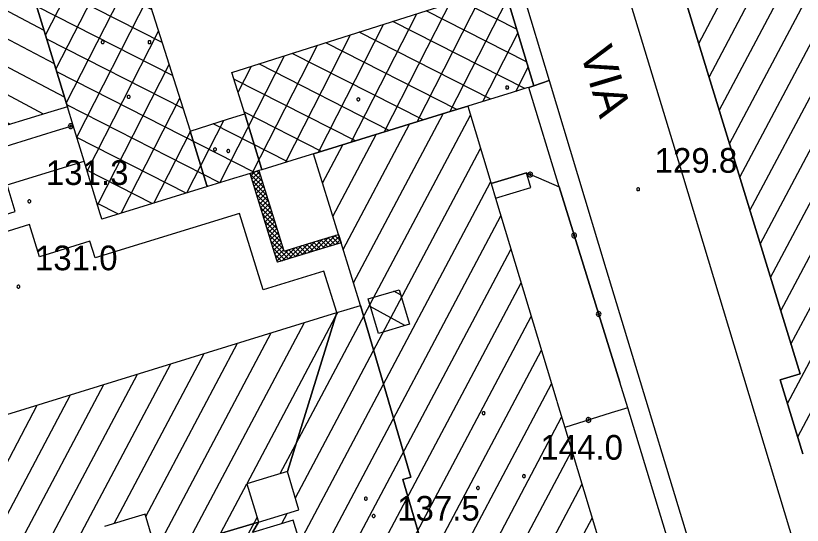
# Model space of a CAD drawing. Extents: x 513373 to 514978, y 5038576 to 5040180.
# Drawn here: x 513597.32 to 513645.09, y 5038663.13 to 5038694.11 of the extents above; entities that cross this region are included whole.
import ezdxf

# ---------------------------------------------------------------- set-up
doc = ezdxf.new("R2010")
doc.units = 0
for name, color, linetype in [('2010300', 7, 'Continuous'), ('3010204', 7, 'Continuous'), ('B1211', 7, 'Continuous'), ('C1131', 7, 'Continuous'), ('C12211', 7, 'Continuous'), ('C1228', 7, 'Continuous'), ('C211113', 7, 'Continuous'), ('C211132', 7, 'Continuous'), ('C2911', 7, 'Continuous'), ('C4114', 7, 'Continuous'), ('CAMP_C12211', 7, 'Continuous'), ('CAMP_C1228', 7, 'Continuous'), ('CAMP_C211132', 7, 'Continuous'), ('CAMP_C4114', 7, 'Continuous'), ('Default', 7, 'Continuous'), ('F12107', 7, 'Continuous'), ('F12131', 7, 'Continuous'), ('F12132', 7, 'Continuous'), ('TOP500', 7, 'Continuous'), ('TOP920', 7, 'Continuous')]:
    doc.layers.add(name, color=color, linetype=linetype)

# ---------------------------------------------------------------- blocks, each defined once
blk = doc.blocks.new('CAMP_2C1236C1')
at = {"layer": 'CAMP_C12211'}
for p, q in [((-31.743, -9.383), (-17.651, 17.232)), ((-32.365, -7.353), (-19.679, 16.607)), ((-32.987, -5.322), (-21.708, 15.982)), ((-31.121, -11.414), (-23.978, 2.077)), ((-30.499, -13.444), (-23.346, 0.066)), ((-29.877, -15.475), (-22.713, -1.945)), ((-29.255, -17.506), (-22.081, -3.957)), ((-28.633, -19.536), (-21.449, -5.968)), ((-28.011, -21.567), (-20.816, -7.979)), ((-27.388, -23.598), (-20.184, -9.991)), ((-27.6, -27.203), (-19.551, -12.002)), ((-26.978, -29.234), (-18.919, -14.013))]:
    blk.add_line(p, q, dxfattribs=at)
blk = doc.blocks.new('CAMP_D0075765')
at = {"layer": 'CAMP_C1228'}
for p, q in [((9.463, 3.83), (12.397, 9.588)), ((12.43, 9.48), (11.803, 9.8)), ((8.828, 5.888), (10.63, 9.424)), ((13.03, 7.491), (9.773, 9.15)), ((8.193, 7.945), (8.619, 8.781)), ((13.629, 5.502), (8.074, 8.333)), ((-13.783, 1.159), (-10.328, 7.941)), ((-8.617, 6.736), (-10.728, 7.812)), ((-14.413, 3.227), (-12.34, 7.294)), ((-13.153, -0.909), (-8.863, 7.511)), ((6.786, -4.73), (13.023, 7.512)), ((-7.98, 4.728), (-12.755, 7.161)), ((-15.043, 5.294), (-14.353, 6.648)), ((-7.343, 2.72), (-14.782, 6.51)), ((14.229, 3.513), (8.69, 6.335)), ((-12.523, -2.976), (-8.217, 5.475)), ((8.784, -4.112), (13.649, 5.437)), ((-6.706, 0.712), (-14.922, 4.898)), ((14.829, 1.524), (9.306, 4.338)), ((-11.893, -5.044), (-7.571, 3.439)), ((10.782, -3.495), (14.275, 3.361)), ((-6.068, -1.296), (-14.315, 2.906)), ((4.787, -5.347), (8.762, 2.453)), ((15.429, -0.465), (9.341, 2.637)), ((15.319, -2.093), (7.305, 1.99)), ((2.789, -5.964), (6.753, 1.815)), ((-11.263, -7.112), (-6.925, 1.403)), ((0.791, -6.582), (4.745, 1.178)), ((13.262, -2.728), (5.27, 1.344)), ((12.78, -2.877), (14.901, 1.286)), ((-5.431, -3.305), (-13.708, 0.913)), ((-1.207, -7.199), (2.737, 0.54)), ((11.205, -3.364), (3.234, 0.698)), ((9.149, -3.999), (1.198, 0.052)), ((-3.205, -7.816), (0.728, -0.097)), ((-10.633, -9.179), (-6.279, -0.633)), ((-2.086, -2.317), (-1.28, -0.735)), ((7.092, -4.635), (-0.838, -0.595)), ((14.778, -2.26), (15.527, -0.79)), ((-1.135, -7.177), (-13.101, -1.08)), ((5.035, -5.27), (-2.343, -1.511)), ((-9.199, -9.668), (-5.633, -2.669)), ((-3.192, -7.812), (-12.494, -3.073)), ((2.978, -5.906), (-1.704, -3.52)), ((-5.203, -8.434), (-2.956, -4.023)), ((0.922, -6.541), (-3.612, -4.232)), ((-7.201, -9.051), (-4.964, -4.661)), ((-5.249, -8.448), (-11.886, -5.066)), ((-7.305, -9.083), (-11.279, -7.059)), ((-9.362, -9.719), (-10.672, -9.052))]:
    blk.add_line(p, q, dxfattribs=at)
blk = doc.blocks.new('CAMP_AE7E8461')
at = {"layer": 'CAMP_C12211'}
for p, q in [((7.76, 8.621), (6.302, 9.393)), ((8.377, 6.597), (4.261, 8.776)), ((8.993, 4.573), (2.219, 8.16)), ((9.61, 2.55), (0.179, 7.543)), ((10.226, 0.526), (-1.863, 6.927)), ((10.843, -1.498), (-3.904, 6.31)), ((11.46, -3.522), (-5.945, 5.694)), ((10.188, -4.546), (-7.987, 5.077)), ((8.146, -5.162), (-10.028, 4.461)), ((6.105, -5.778), (-11.646, 3.62)), ((4.064, -6.395), (-11.036, 1.6)), ((2.023, -7.012), (-10.426, -0.42)), ((-0.018, -7.628), (-9.816, -2.441)), ((-2.06, -8.245), (-9.205, -4.461)), ((-4.101, -8.861), (-8.595, -6.481)), ((-6.142, -9.478), (-7.985, -8.502))]:
    blk.add_line(p, q, dxfattribs=at)
blk = doc.blocks.new('CAMP_13884420')
at = {"layer": 'CAMP_C12211'}
for p, q in [((3.521, 4.937), (14.114, 24.943)), ((7.011, 14.734), (12.456, 25.017)), ((6.386, 16.759), (10.427, 24.39)), ((5.76, 18.783), (8.397, 23.763)), ((5.135, 20.807), (6.368, 23.136)), ((3.486, 1.666), (14.73, 22.901)), ((3.759, -1.025), (15.346, 20.859)), ((-1.731, -14.6), (15.962, 18.817)), ((0.298, -13.973), (16.578, 16.775)), ((2.327, -13.346), (17.194, 14.733)), ((5.93, 12.693), (6.065, 12.948)), ((0.551, 2.533), (5.93, 12.693)), ((4.356, -12.719), (17.811, 12.691)), ((-3.398, -1.719), (4.036, 12.321)), ((-4.99, -1.52), (2.007, 11.694)), ((-5.604, 0.525), (-0.023, 11.066)), ((6.386, -12.092), (18.427, 10.65)), ((-7.523, 0.107), (-2.052, 10.439)), ((-12.88, -6.805), (-4.081, 9.812)), ((-13.494, -4.76), (-6.11, 9.185)), ((8.415, -11.465), (19.043, 8.608)), ((-13.916, -2.351), (-8.14, 8.558)), ((-15.597, -2.321), (-10.169, 7.931)), ((-19.19, -5.901), (-12.198, 7.304)), ((-19.815, -3.877), (-14.228, 6.677)), ((10.444, -10.838), (19.659, 6.566)), ((-20.441, -1.852), (-16.257, 6.05)), ((-21.066, 0.172), (-18.286, 5.423)), ((-21.692, 2.196), (-20.315, 4.796)), ((2.57, 3.14), (3.521, 4.937)), ((12.474, -10.211), (20.276, 4.524)), ((-1.379, -1.113), (0.542, 2.515)), ((13.962, -10.605), (20.892, 2.482)), ((2.658, 0.1), (2.988, 0.725)), ((0.639, -0.506), (1.156, 0.47)), ((14.588, -12.629), (21.508, 0.441)), ((-16.063, -16.022), (-7.934, -0.671)), ((-7.819, -16.481), (0.639, -0.506)), ((-9.849, -17.109), (-1.379, -1.113)), ((-5.416, -2.326), (-5.086, -1.702)), ((-4.529, -3.857), (-3.398, -1.719)), ((15.762, -13.618), (22.124, -1.601)), ((-7.435, -2.933), (-7.104, -2.309)), ((-5.79, -15.854), (1.428, -2.221)), ((-3.761, -15.227), (3.076, -2.314)), ((-15.437, -18.047), (-7.474, -3.007)), ((-17.452, -5.824), (-16.246, -3.547)), ((17.782, -13.008), (22.74, -3.643)), ((-15.509, -5.36), (-15.178, -4.735)), ((-11.878, -17.736), (-4.998, -4.741)), ((-13.907, -18.363), (-6.86, -5.053)), ((19.802, -12.399), (23.356, -5.685)), ((-18.564, -7.925), (-17.452, -5.824)), ((-17.939, -9.949), (-15.824, -5.955)), ((-16.688, -13.998), (-13.072, -7.168)), ((-17.314, -11.974), (-15.09, -7.775)), ((21.822, -11.789), (23.972, -7.727)), ((23.842, -11.179), (24.589, -9.769))]:
    blk.add_line(p, q, dxfattribs=at)
blk = doc.blocks.new('CAMP_5D255280')
at = {"layer": 'CAMP_C211132'}
for p, q in [((0.497, 0.583), (0.089, 0.807)), ((0.759, -1.273), (-1.345, -0.117))]:
    blk.add_line(p, q, dxfattribs=at)
blk = doc.blocks.new('CAMP_2C38B86D')
at = {"layer": 'CAMP_C4114'}
for p, q in [((-2.08, 3.138), (-1.86, 3.358)), ((-2.013, 2.922), (-1.56, 3.375)), ((-1.503, 3.19), (-1.716, 3.403)), ((-1.249, 2.37), (-2.108, 3.229)), ((-1.946, 2.706), (-1.493, 3.159)), ((-1.376, 2.78), (-1.932, 3.336)), ((-1.88, 2.49), (-1.426, 2.943)), ((-1.121, 1.96), (-1.982, 2.82)), ((-0.994, 1.55), (-1.855, 2.411)), ((-1.813, 2.274), (-1.359, 2.727)), ((-1.746, 2.058), (-1.293, 2.511)), ((-0.867, 1.14), (-1.729, 2.001)), ((-1.679, 1.842), (-1.226, 2.295)), ((-1.612, 1.626), (-1.159, 2.079)), ((-0.74, 0.73), (-1.602, 1.592)), ((-1.546, 1.409), (-1.092, 1.864)), ((-1.479, 1.193), (-1.025, 1.648)), ((-0.613, 0.32), (-1.476, 1.183)), ((-1.412, 0.977), (-0.958, 1.432)), ((-1.345, 0.761), (-0.891, 1.216)), ((-1.279, 0.545), (-0.824, 1)), ((-0.486, -0.09), (-1.349, 0.773)), ((-1.212, 0.329), (-0.757, 0.784)), ((-1.145, 0.113), (-0.69, 0.568)), ((-0.358, -0.5), (-1.223, 0.364)), ((-1.078, -0.103), (-0.623, 0.352)), ((-1.012, -0.319), (-0.556, 0.136)), ((-0.231, -0.91), (-1.096, -0.046)), ((-0.104, -1.32), (-0.97, -0.455)), ((-0.945, -0.535), (-0.489, -0.079)), ((-0.878, -0.751), (-0.422, -0.295)), ((0.216, -1.924), (-0.843, -0.864)), ((-0.811, -0.967), (-0.355, -0.511)), ((-0.744, -1.183), (-0.288, -0.727)), ((-0.678, -1.399), (-0.221, -0.943)), ((1.029, -1.673), (1.84, -0.861)), ((1.438, -1.546), (2.25, -0.735)), ((2.161, -1.323), (1.733, -0.895)), ((1.848, -1.42), (2.659, -0.608)), ((2.377, -1.256), (1.949, -0.828)), ((2.593, -1.189), (2.165, -0.761)), ((2.257, -1.293), (3.069, -0.482)), ((2.809, -1.123), (2.381, -0.694)), ((3.026, -1.056), (2.597, -0.627)), ((2.666, -1.167), (3.28, -0.553)), ((3.242, -0.989), (2.813, -0.561)), ((3.366, -0.831), (3.029, -0.494)), ((3.075, -1.041), (3.347, -0.769)), ((0, -1.99), (-0.717, -1.274)), ((-0.611, -1.615), (-0.154, -1.159)), ((-0.544, -1.832), (-0.087, -1.375)), ((-0.477, -2.048), (0.203, -1.368)), ((-0.199, -2.052), (0.612, -1.241)), ((0.432, -1.857), (0.005, -1.429)), ((0.211, -1.925), (1.022, -1.114)), ((0.649, -1.79), (0.221, -1.362)), ((0.865, -1.723), (0.437, -1.295)), ((0.62, -1.799), (1.431, -0.988)), ((1.081, -1.657), (0.653, -1.229)), ((1.297, -1.59), (0.869, -1.162)), ((1.513, -1.523), (1.085, -1.095)), ((1.729, -1.456), (1.301, -1.028)), ((1.945, -1.39), (1.517, -0.961)), ((-0.216, -2.057), (-0.59, -1.683)), ((-0.432, -2.124), (-0.464, -2.092))]:
    blk.add_line(p, q, dxfattribs=at)
blk = doc.blocks.new('03080200')
at = {"layer": 'Default'}
for p, q in [((-0.139, 0.046), (-0.146, 0)), ((-0.146, 0), (-0.139, -0.046)), ((-0.118, 0.086), (-0.139, 0.046)), ((-0.086, 0.118), (-0.118, 0.086)), ((-0.046, 0.139), (-0.086, 0.118)), ((0, 0.146), (-0.046, 0.139)), ((-0.042, 0.014), (-0.045, 0)), ((-0.045, 0), (-0.042, -0.014)), ((-0.036, 0.026), (-0.042, 0.014)), ((-0.026, 0.036), (-0.036, 0.026)), ((-0.014, 0.042), (-0.026, 0.036)), ((0, 0.045), (-0.014, 0.042)), ((0.046, 0.139), (0, 0.146)), ((0.014, 0.042), (0, 0.045)), ((0.026, 0.036), (0.014, 0.042)), ((0.036, 0.026), (0.026, 0.036)), ((0.042, 0.014), (0.036, 0.026)), ((0.045, 0), (0.042, 0.014)), ((0.042, -0.014), (0.045, 0)), ((0.086, 0.118), (0.046, 0.139)), ((0.118, 0.086), (0.086, 0.118)), ((0.139, 0.046), (0.118, 0.086)), ((0.146, 0), (0.139, 0.046)), ((0.139, -0.046), (0.146, 0)), ((-0.139, -0.046), (-0.118, -0.086)), ((-0.118, -0.086), (-0.086, -0.118)), ((-0.086, -0.118), (-0.046, -0.139)), ((-0.046, -0.139), (0, -0.146)), ((-0.042, -0.014), (-0.036, -0.026)), ((-0.036, -0.026), (-0.026, -0.036)), ((-0.026, -0.036), (-0.014, -0.042)), ((-0.014, -0.042), (0, -0.045)), ((0, -0.045), (0.014, -0.042)), ((0, -0.146), (0.046, -0.139)), ((0.014, -0.042), (0.026, -0.036)), ((0.026, -0.036), (0.036, -0.026)), ((0.036, -0.026), (0.042, -0.014)), ((0.046, -0.139), (0.086, -0.118)), ((0.086, -0.118), (0.118, -0.086)), ((0.118, -0.086), (0.139, -0.046))]:
    blk.add_line(p, q, dxfattribs=at)
blk = doc.blocks.new('08020400')
at = {"layer": 'Default'}
for p, q in [((-0.086, 0.028), (-0.09, 0)), ((-0.09, 0), (-0.086, -0.028)), ((-0.073, 0.053), (-0.086, 0.028)), ((-0.053, 0.073), (-0.073, 0.053)), ((-0.028, 0.086), (-0.053, 0.073)), ((0, 0.09), (-0.028, 0.086)), ((0.028, 0.086), (0, 0.09)), ((0.053, 0.073), (0.028, 0.086)), ((0.073, 0.053), (0.053, 0.073)), ((0.086, 0.028), (0.073, 0.053)), ((0.09, 0), (0.086, 0.028)), ((0.086, -0.028), (0.09, 0)), ((-0.086, -0.028), (-0.073, -0.053)), ((-0.073, -0.053), (-0.053, -0.073)), ((-0.053, -0.073), (-0.028, -0.086)), ((-0.028, -0.086), (0, -0.09)), ((0, -0.09), (0.028, -0.086)), ((0.028, -0.086), (0.053, -0.073)), ((0.053, -0.073), (0.073, -0.053)), ((0.073, -0.053), (0.086, -0.028))]:
    blk.add_line(p, q, dxfattribs=at)
blk = doc.blocks.new('NSIMB25')
at = {"layer": 'Default'}
for p, q in [((-0.086, 0.028), (-0.09, 0)), ((-0.09, 0), (-0.086, -0.028)), ((-0.073, 0.053), (-0.086, 0.028)), ((-0.053, 0.073), (-0.073, 0.053)), ((-0.028, 0.086), (-0.053, 0.073)), ((0, 0.09), (-0.028, 0.086)), ((0.028, 0.086), (0, 0.09)), ((0.053, 0.073), (0.028, 0.086)), ((0.073, 0.053), (0.053, 0.073)), ((0.086, 0.028), (0.073, 0.053)), ((0.09, 0), (0.086, 0.028)), ((0.086, -0.028), (0.09, 0)), ((-0.086, -0.028), (-0.073, -0.053)), ((-0.073, -0.053), (-0.053, -0.073)), ((-0.053, -0.073), (-0.028, -0.086)), ((-0.028, -0.086), (0, -0.09)), ((0, -0.09), (0.028, -0.086)), ((0.028, -0.086), (0.053, -0.073)), ((0.053, -0.073), (0.073, -0.053)), ((0.073, -0.053), (0.086, -0.028))]:
    blk.add_line(p, q, dxfattribs=at)
blk = doc.blocks.new('A$C3704598A')
at = {"layer": '2010300'}
blk.add_lwpolyline([(257.279, -696.425), (255.429, -690.383)], dxfattribs=at)
at = {"layer": '3010204'}
for points in [[(223.745, -696.313), (228.419, -694.868)], [(243.776, -704.079), (242.995, -701.55), (239.309, -702.688), (237.873, -698.042), (229.091, -700.755), (228.776, -699.737), (225.716, -700.682), (225.112, -698.727), (222.436, -699.554)]]:
    blk.add_lwpolyline(points, dxfattribs=at)
at = {"layer": 'B1211'}
for points in [[(314.878, -654.761), (269.808, -668.647), (269.785, -668.574), (269.568, -667.868), (268.566, -668.177), (258.4, -671.309), (261.926, -682.527), (261.949, -682.598), (262.994, -682.277), (263.997, -681.97), (271.91, -707.801), (270.707, -708.17), (272.084, -712.665)], [(283.252, -756.933), (264.211, -693.769), (259.814, -679.302), (257.474, -671.601), (257.45, -671.522), (257.371, -671.263), (257.393, -670.826), (257.636, -670.153), (257.934, -669.828), (258.151, -669.592), (258.407, -669.448), (270.456, -665.66), (287.698, -660.31)], [(253.398, -679.084), (256.672, -689.963), (255.736, -690.288), (253.915, -684.25)]]:
    blk.add_lwpolyline(points, dxfattribs=at)
blk.add_lwpolyline([(271.884, -740.192), (271.049, -741.525), (270.763, -740.582), (268.839, -734.233), (267.364, -729.37), (266.632, -726.953), (261.45, -709.862), (260.968, -708.309), (257.279, -696.425), (255.429, -690.383), (255.68, -690.305), (255.736, -690.288), (256.672, -689.963), (260.111, -701.391), (266.569, -722.666)], close=True, dxfattribs=at)
at = {"layer": 'C1131'}
for points in [[(272.084, -712.665), (270.707, -708.17), (271.91, -707.801), (263.997, -681.97), (262.994, -682.277), (261.949, -682.598), (261.926, -682.527), (258.4, -671.309), (268.566, -668.177), (269.568, -667.868), (269.785, -668.574), (269.808, -668.647), (314.878, -654.761)], [(232.824, -718.667), (239.009, -716.808), (238.662, -717.437)], [(241.829, -719.027), (241.129, -716.696), (240.126, -716.998), (238.662, -717.437), (239.009, -716.808), (241.476, -716.066), (240.775, -713.736), (239.772, -714.038), (238.309, -714.478), (238.99, -716.742), (239.009, -716.808), (232.824, -718.667), (232.124, -716.337), (231.121, -716.639), (229.657, -717.078)], [(218.67, -723.194), (215.467, -712.826), (219.25, -711.657), (243.776, -704.079), (244.203, -703.946), (245.205, -703.637), (248.265, -714.071), (247.781, -714.213), (251.152, -725.672)]]:
    blk.add_lwpolyline(points, dxfattribs=at)
for points in [[(208.476, -697.287), (208.214, -697.366), (208.194, -697.3), (207.59, -695.3), (205.129, -687.152), (204.031, -683.517), (210.127, -681.676), (213.684, -680.602), (215.397, -680.085), (217.397, -679.48), (221.642, -678.198), (222.193, -678.032), (223.197, -677.729), (224.484, -681.955), (224.51, -682.039), (227.413, -691.567), (226.409, -691.87), (222.271, -693.12), (216.656, -694.816)], [(230.797, -680.201), (234.844, -692.956), (234.87, -693.036), (235.889, -696.34), (235.912, -696.413), (229.494, -698.396), (229.471, -698.323), (229.393, -698.065), (228.419, -694.868), (227.756, -692.691), (227.413, -691.567), (224.51, -682.039), (229.748, -680.358), (230.605, -680.082), (230.752, -680.059), (230.772, -680.122)], [(255.736, -690.288), (255.68, -690.305), (255.429, -690.383), (255.325, -690.415), (254.427, -690.692), (251.724, -691.528), (250.722, -691.837), (242.358, -694.422), (241.357, -694.731), (239.216, -695.392), (239.194, -695.319), (238.194, -691.981), (237.398, -689.477), (249.655, -685.587), (252.914, -684.564), (253.915, -684.25)], [(253.285, -730.7), (252.739, -730.865), (252.718, -730.797), (251.493, -726.833), (251.152, -725.672), (247.781, -714.213), (248.265, -714.071), (245.205, -703.637), (244.029, -699.829), (243.87, -699.317), (242.358, -694.422), (250.722, -691.837), (251.724, -691.528), (253.122, -696.162), (253.143, -696.229), (253.412, -697.122), (257.134, -709.456), (257.16, -709.544), (257.615, -711.051), (262.688, -727.862), (259.089, -728.949), (258.083, -729.252)], [(239.216, -695.392), (239.047, -695.444), (238.506, -695.612), (238.046, -695.754), (237.505, -695.921), (235.912, -696.413), (235.889, -696.34), (234.87, -693.036), (237.194, -692.299), (238.194, -691.981), (239.194, -695.319)]]:
    blk.add_lwpolyline(points, close=True, dxfattribs=at)
at = {"layer": 'C12211'}
for points in [[(272.084, -712.665), (270.707, -708.17), (271.91, -707.801), (263.997, -681.97), (262.994, -682.277), (261.949, -682.598), (261.926, -682.527), (258.4, -671.309), (268.566, -668.177), (269.568, -667.868), (269.785, -668.574), (269.808, -668.647), (314.878, -654.761)], [(218.67, -723.194), (215.467, -712.826), (219.25, -711.657), (243.776, -704.079), (240.775, -713.736), (239.772, -714.038), (238.309, -714.478), (238.99, -716.742), (239.009, -716.808), (238.662, -717.437)], [(232.824, -718.667), (232.124, -716.337), (231.121, -716.639), (229.657, -717.078)], [(241.829, -719.027), (241.129, -716.696), (240.126, -716.998), (238.662, -717.437), (239.009, -716.808), (241.476, -716.066), (240.775, -713.736), (243.776, -704.079), (244.203, -703.946), (245.205, -703.637), (244.029, -699.829), (243.87, -699.317), (242.358, -694.422), (250.722, -691.837), (251.724, -691.528), (253.122, -696.162), (253.143, -696.229), (253.412, -697.122), (257.134, -709.456), (257.16, -709.544), (257.615, -711.051), (262.688, -727.862)]]:
    blk.add_lwpolyline(points, dxfattribs=at)
blk.add_lwpolyline([(208.476, -697.287), (208.214, -697.366), (208.194, -697.3), (207.59, -695.3), (205.129, -687.152), (204.031, -683.517), (210.127, -681.676), (213.684, -680.602), (215.397, -680.085), (217.397, -679.48), (221.642, -678.198), (222.193, -678.032), (223.197, -677.729), (224.484, -681.955), (224.51, -682.039), (227.413, -691.567), (226.409, -691.87), (222.271, -693.12), (216.656, -694.816)], close=True, dxfattribs=at)
at = {"layer": 'C1228'}
for points in [[(230.797, -680.201), (234.844, -692.956), (234.87, -693.036), (237.194, -692.299), (238.194, -691.981), (237.398, -689.477), (249.655, -685.587)], [(253.915, -684.25), (255.736, -690.288), (255.68, -690.305), (255.429, -690.383), (255.325, -690.415), (254.427, -690.692), (251.724, -691.528), (250.722, -691.837), (242.358, -694.422), (241.357, -694.731), (239.216, -695.392), (239.047, -695.444), (238.506, -695.612), (238.046, -695.754), (237.505, -695.921), (235.912, -696.413), (229.494, -698.396), (229.471, -698.323), (229.393, -698.065), (228.419, -694.868), (227.756, -692.691), (227.413, -691.567), (224.51, -682.039)]]:
    blk.add_lwpolyline(points, dxfattribs=at)
at = {"layer": 'C211113'}
blk.add_lwpolyline([(253.143, -696.229), (253.412, -697.122), (255.557, -696.475), (255.519, -696.349), (255.288, -695.582), (254.364, -695.86)], close=True, dxfattribs=at)
at = {"layer": 'C211132'}
blk.add_lwpolyline([(248.18, -704.781), (246.297, -705.34), (245.675, -703.245), (247.558, -702.686)], close=True, dxfattribs=at)
at = {"layer": 'C2911'}
for points in [[(208.905, -698.538), (215.486, -696.502), (216.487, -696.192), (216.724, -696.956), (217.655, -699.967), (221.024, -698.924), (222.134, -698.581), (224.245, -697.928), (223.745, -696.313), (223.722, -696.24), (223.073, -694.139), (226.754, -693.001), (227.756, -692.691)], [(253.143, -696.229), (254.364, -695.86), (255.288, -695.582), (256.019, -695.891), (257.279, -696.425), (260.968, -708.309)], [(261.45, -709.862), (260.449, -710.172), (257.615, -711.051)]]:
    blk.add_lwpolyline(points, dxfattribs=at)
at = {"layer": 'C4114'}
blk.add_lwpolyline([(243.87, -699.317), (244.029, -699.829), (243.027, -700.138), (240.177, -701.018), (240.154, -700.945), (239.996, -700.434), (238.506, -695.612), (239.047, -695.444), (240.542, -700.265), (240.565, -700.338), (242.869, -699.626)], close=True, dxfattribs=at)
at = {"layer": 'C2911'}
for p, rotation in [((227.608, -692.737), 17.17990437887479), ((255.527, -695.683), -22.949039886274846), ((258.197, -699.383), -72.75114271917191), ((259.68, -704.158), -72.75114271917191), ((259.063, -710.602), -162.7753308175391)]:
    blk.add_blockref('03080200', p, dxfattribs=dict(at, rotation=rotation))
at = {"layer": 'CAMP_C12211'}
for name, p in [('CAMP_2C1236C1', (298.747, -682.401)), ('CAMP_AE7E8461', (215.775, -687.46)), ('CAMP_13884420', (237.772, -717.007))]:
    blk.add_blockref(name, p, dxfattribs=at)
at = {"layer": 'CAMP_C1228'}
blk.add_blockref('CAMP_D0075765', (239.867, -688.365), dxfattribs=at)
at = {"layer": 'CAMP_C211132'}
blk.add_blockref('CAMP_5D255280', (247.155, -703.586), dxfattribs=at)
at = {"layer": 'CAMP_C4114'}
blk.add_blockref('CAMP_2C38B86D', (240.629, -698.888), dxfattribs=at)
at = {"layer": 'F12107'}
for p in [(262.079, -696.573), (225.1, -697.314), (224.437, -702.501), (255.139, -714.018)]:
    blk.add_blockref('08020400', p, dxfattribs=at)
at = {"layer": 'F12131'}
for p in [(231.132, -690.956), (245.085, -691.116), (236.377, -694.156), (252.689, -710.191), (245.536, -715.383)]:
    blk.add_blockref('NSIMB25', p, dxfattribs=at)
at = {"layer": 'F12132'}
for p in [(229.547, -687.634), (232.396, -687.634), (254.123, -690.388), (237.177, -694.254), (252.345, -714.742), (246.013, -716.442)]:
    blk.add_blockref('NSIMB25', p, dxfattribs=at)
at = {"layer": 'TOP500'}
blk.add_text('VIA', height=2, rotation=286.6283, dxfattribs=at).set_placement((258.535, -688.215))
at = {"layer": 'TOP920'}
for s, p in [('129.8', (263.079, -695.573)), ('131.3', (226.1, -696.314)), ('131.0', (225.437, -701.501)), ('144.0', (256.139, -713.018)), ('137.5', (247.438, -716.723))]:
    blk.add_text(s, height=1.5, dxfattribs=at).set_placement(p)

msp = doc.modelspace()

# ---------------------------------------------------------------- block references
at = {"layer": 'Default'}
msp.add_blockref('A$C3704598A', (513373.046, 5039380.14), dxfattribs=at)

doc.saveas('drawing.dxf')
